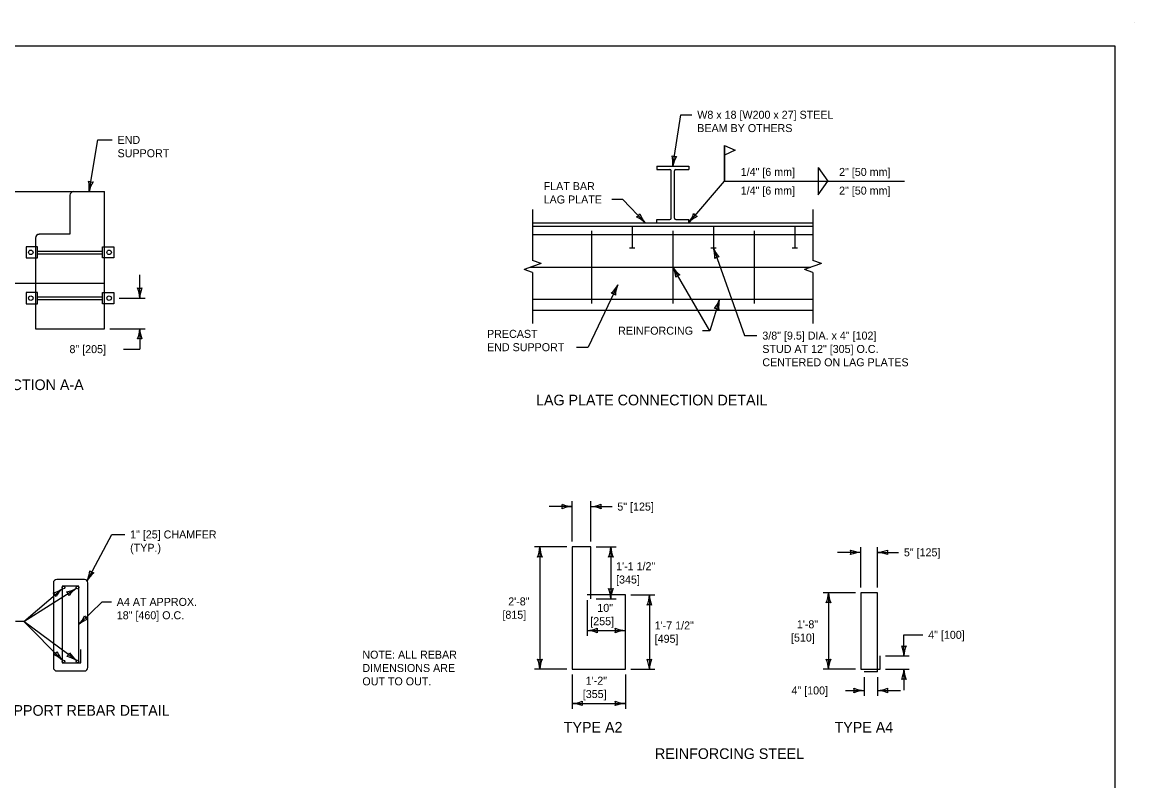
# Model space of a CAD drawing. Extents: x 49987.2 to 50044, y 49982.5 to 50011.4.
# Drawn here: x 50008.56 to 50016.9, y 49993.49 to 49999.18 of the extents above; entities that cross this region are included whole.
import ezdxf

# ---------------------------------------------------------------- set-up
doc = ezdxf.new("R2010")
doc.units = 0
for name, color, linetype in [('Level 1', 7, 'Continuous'), ('Level 2', 7, 'Continuous'), ('Level 3', 7, 'Continuous'), ('Level 4', 7, 'Continuous'), ('Level 5', 7, 'Continuous'), ('Level 6', 7, 'Continuous')]:
    doc.layers.add(name, color=color, linetype=linetype)

msp = doc.modelspace()

# ---------------------------------------------------------------- linework, layer by layer
at = {"layer": 'Level 1'}
for p, q in [((50016.9001, 49999.1756), (50016.9001, 49999.1756)), ((50013.3156, 49998.0969), (50013.5556, 49998.0969)), ((50013.3156, 49998.0969), (50013.3156, 49998.0719)), ((50013.3156, 49998.0719), (50013.4131, 49998.0719)), ((50013.4581, 49998.0719), (50013.5556, 49998.0719)), ((50013.5556, 49998.0969), (50013.5556, 49998.0719)), ((50013.4231, 49997.7069), (50013.4231, 49998.0619)), ((50013.4481, 49997.7069), (50013.4481, 49998.0619)), ((50007.5791, 49997.9057), (50009.174, 49997.9057)), ((50009.174, 49996.8763), (50009.174, 49997.9057)), ((50008.9153, 49997.8776), (50008.9153, 49997.5851)), ((50012.3846, 49997.6719), (50014.4864, 49997.6719)), ((50013.3156, 49997.6719), (50013.3156, 49997.6969)), ((50013.3156, 49997.6969), (50013.4131, 49997.6969)), ((50013.4581, 49997.6969), (50013.5556, 49997.6969)), ((50013.5556, 49997.6719), (50013.5556, 49997.6969)), ((50008.9153, 49997.5851), (50008.6847, 49997.5851)), ((50012.3846, 49997.6469), (50014.4864, 49997.6469)), ((50014.4864, 49997.5806), (50012.3846, 49997.5806)), ((50012.8256, 49997.6106), (50012.8256, 49997.0669)), ((50013.1306, 49997.6469), (50013.1306, 49997.4819)), ((50013.4356, 49997.6106), (50013.4356, 49997.0669)), ((50013.7406, 49997.6469), (50013.7406, 49997.4819)), ((50014.0456, 49997.6106), (50014.0456, 49997.0669)), ((50014.3506, 49997.6469), (50014.3506, 49997.4819)), ((50008.6565, 49997.5569), (50008.6565, 49996.8763)), ((50008.6712, 49997.46), (50009.1594, 49997.46)), ((50008.6712, 49997.44), (50009.1594, 49997.44)), ((50013.1506, 49997.4819), (50013.1106, 49997.4819)), ((50013.7606, 49997.4819), (50013.7206, 49997.4819)), ((50014.3706, 49997.4819), (50014.3306, 49997.4819)), ((50012.3692, 49997.3387), (50014.471, 49997.3387)), ((50007.5791, 49997.2194), (50008.6565, 49997.2194)), ((50008.6712, 49997.1169), (50009.1594, 49997.1169)), ((50008.6712, 49997.0969), (50009.1594, 49997.0969)), ((50014.4864, 49997.0969), (50012.3846, 49997.0969)), ((50012.3846, 49997.0169), (50014.4864, 49997.0169)), ((50008.6565, 49996.8763), (50009.174, 49996.8763)), ((50012.822, 49995.2403), (50012.6814, 49995.2403)), ((50012.6814, 49995.2403), (50012.6814, 49994.3234)), ((50012.822, 49994.8522), (50012.822, 49995.2403)), ((50009.0248, 49994.9971), (50008.816, 49994.9971)), ((50008.791, 49994.9721), (50008.791, 49994.3358)), ((50008.8574, 49994.9463), (50008.8574, 49994.3725)), ((50008.9824, 49994.9463), (50008.8574, 49994.9463)), ((50008.9824, 49994.3725), (50008.9824, 49994.9463)), ((50009.0498, 49994.3358), (50009.0498, 49994.9721)), ((50013.0807, 49994.8803), (50012.7939, 49994.8803)), ((50013.0807, 49994.3234), (50013.0807, 49994.8803)), ((50014.8457, 49994.8972), (50014.8457, 49994.3234)), ((50014.9707, 49994.8972), (50014.8457, 49994.8972)), ((50014.9707, 49994.3043), (50014.9707, 49994.8972)), ((50008.9981, 49994.3725), (50008.9981, 49994.4715)), ((50014.9898, 49994.3234), (50014.9898, 49994.4234)), ((50008.8574, 49994.3725), (50008.9981, 49994.3725)), ((50012.6814, 49994.3234), (50013.0807, 49994.3234)), ((50014.8457, 49994.3234), (50014.9898, 49994.3234)), ((50008.816, 49994.3108), (50009.0248, 49994.3108)), ((50014.9707, 49994.3043), (50014.8707, 49994.3043))]:
    msp.add_line(p, q, dxfattribs=at)
for points in [[(49999.3835, 49998.9992), (50016.7501, 49998.9992), (50016.7501, 49987.7988), (49999.3835, 49987.7988)], [(50008.5868, 49997.4079), (50008.6712, 49997.4079), (50008.6712, 49997.4922), (50008.5868, 49997.4922)], [(50009.2438, 49997.4079), (50009.1594, 49997.4079), (50009.1594, 49997.4922), (50009.2438, 49997.4922)], [(50008.5868, 49997.0647), (50008.6712, 49997.0647), (50008.6712, 49997.1491), (50008.5868, 49997.1491)], [(50009.2438, 49997.0647), (50009.1594, 49997.0647), (50009.1594, 49997.1491), (50009.2438, 49997.1491)]]:
    msp.add_lwpolyline(points, close=True, dxfattribs=at)
for centre, radius in [((50008.6216, 49997.45), 0.0169), ((50009.2089, 49997.45), 0.0169), ((50008.6216, 49997.1069), 0.0169), ((50009.2089, 49997.1069), 0.0169), ((50008.8674, 49994.9363), 0.01), ((50008.9724, 49994.9363), 0.01), ((50008.8674, 49994.3825), 0.01), ((50008.9724, 49994.3825), 0.01)]:
    msp.add_circle(centre, radius, dxfattribs=at)
for centre, radius, start, end in [((50013.4131, 49998.0619), 0.01, 360, 90), ((50013.4581, 49998.0619), 0.01, 90, 180), ((50008.9434, 49997.8776), 0.0281, 90, 180), ((50013.4131, 49997.7069), 0.01, 270, 360), ((50013.4581, 49997.7069), 0.01, 180, 270), ((50008.6847, 49997.5569), 0.0281, 90, 180), ((50008.816, 49994.9721), 0.025, 90, 180), ((50009.0248, 49994.9721), 0.025, 0, 90), ((50008.816, 49994.3358), 0.025, 180, 270), ((50009.0248, 49994.3358), 0.025, 270, 0)]:
    msp.add_arc(centre, radius, start, end, dxfattribs=at)
at = {"layer": 'Level 3'}
for p, q in [((50013.4356, 49998.0969), (50013.4951, 49998.4819)), ((50013.4951, 49998.4819), (50013.5795, 49998.4819)), ((50009.0587, 49997.9057), (50009.1254, 49998.2932)), ((50009.1254, 49998.2932), (50009.2324, 49998.2932)), ((50013.8228, 49998.2504), (50013.9026, 49998.2151)), ((50013.8228, 49998.2504), (50013.8228, 49997.983)), ((50013.8228, 49997.983), (50013.8228, 49998.2504)), ((50013.8228, 49997.983), (50013.8228, 49998.2504)), ((50013.9026, 49998.2151), (50013.8228, 49998.1799)), ((50014.5261, 49998.0856), (50014.5261, 49997.8805)), ((50014.5261, 49998.0856), (50014.5993, 49997.983)), ((50013.5556, 49997.6719), (50013.8228, 49997.983)), ((50013.8228, 49997.983), (50015.1745, 49997.983)), ((50014.5261, 49997.8805), (50014.5993, 49997.983)), ((50013.0625, 49997.8463), (50012.9791, 49997.8463)), ((50013.2293, 49997.6719), (50013.0625, 49997.8463)), ((50013.7406, 49997.4819), (50013.9739, 49996.8255)), ((50013.7146, 49996.8623), (50013.4356, 49997.3387)), ((50009.4387, 49997.1069), (50009.4387, 49997.2804)), ((50013.023, 49997.2052), (50012.8004, 49996.7387)), ((50013.7864, 49997.0969), (50013.7146, 49996.8623)), ((50009.214, 49996.8763), (50009.4787, 49996.8763)), ((50009.4387, 49996.8763), (50009.4387, 49996.724)), ((50013.7146, 49996.8623), (50013.6597, 49996.8623)), ((50013.9739, 49996.8255), (50014.0674, 49996.8255)), ((50012.7131, 49996.7387), (50012.8004, 49996.7387)), ((50009.3167, 49996.724), (50009.4387, 49996.724)), ((50012.6814, 49995.2803), (50012.6814, 49995.5833)), ((50012.822, 49995.2803), (50012.822, 49995.5833)), ((50012.6814, 49995.5433), (50012.5079, 49995.5433)), ((50012.822, 49995.5433), (50012.9801, 49995.5433)), ((50009.0446, 49994.9873), (50009.2289, 49995.3344)), ((50009.2289, 49995.3344), (50009.3265, 49995.3344)), ((50012.6414, 49995.2403), (50012.3987, 49995.2403)), ((50012.4387, 49995.2403), (50012.4387, 49994.3234)), ((50012.862, 49995.2403), (50013.0109, 49995.2403)), ((50012.9709, 49995.2403), (50012.9709, 49994.8522)), ((50014.8457, 49994.9372), (50014.8457, 49995.2402)), ((50014.9707, 49994.9372), (50014.9707, 49995.2402)), ((50014.8457, 49995.2002), (50014.6723, 49995.2002)), ((50014.9707, 49995.2002), (50015.1289, 49995.2002)), ((50008.5685, 49994.682), (50008.964, 49994.9309)), ((50008.5685, 49994.682), (50008.8598, 49994.9298)), ((50008.9824, 49994.6594), (50009.1569, 49994.8283)), ((50009.1569, 49994.8283), (50009.2265, 49994.8283)), ((50012.7939, 49994.8403), (50012.7939, 49994.5737)), ((50012.862, 49994.8522), (50013.0109, 49994.8522)), ((50013.1207, 49994.8803), (50013.3002, 49994.8803)), ((50013.2602, 49994.8803), (50013.2602, 49994.3234)), ((50014.8057, 49994.8972), (50014.5631, 49994.8972)), ((50014.6031, 49994.8972), (50014.6031, 49994.3234)), ((50008.5685, 49994.682), (50008.5063, 49994.682)), ((50008.8603, 49994.3896), (50008.5685, 49994.682)), ((50008.9644, 49994.3884), (50008.5685, 49994.682)), ((50012.7939, 49994.6137), (50013.0807, 49994.6137)), ((50015.1693, 49994.4234), (50015.1693, 49994.5815)), ((50015.1693, 49994.5815), (50015.3112, 49994.5815)), ((50015.0298, 49994.4234), (50015.2093, 49994.4234)), ((50012.6414, 49994.3234), (50012.3987, 49994.3234)), ((50013.1207, 49994.3234), (50013.3002, 49994.3234)), ((50014.8057, 49994.3234), (50014.5631, 49994.3234)), ((50015.0298, 49994.3234), (50015.2093, 49994.3234)), ((50015.1693, 49994.3234), (50015.1693, 49994.1653)), ((50012.6814, 49994.2834), (50012.6814, 49994.0275)), ((50013.0807, 49994.2834), (50013.0807, 49994.0275)), ((50014.8707, 49994.2643), (50014.8707, 49994.1244)), ((50014.9707, 49994.2643), (50014.9707, 49994.1244)), ((50014.7308, 49994.1644), (50014.8707, 49994.1644)), ((50014.9707, 49994.1644), (50015.1442, 49994.1644)), ((50012.6814, 49994.0675), (50013.0807, 49994.0675))]:
    msp.add_line(p, q, dxfattribs=at)
for centre, radius, start, end in [((50013.4552, 49998.2236), 0.0548, 243.35801, 279.08037), ((50013.2039, 49998.121), 0.233, 354.0465, 13.29635), ((50013.6538, 49998.0539), 0.2223, 148.6752, 168.85871), ((50009.0805, 49998.032), 0.0548, 242.37449, 278.09685), ((50008.8274, 49997.9338), 0.233, 353.06298, 12.31283), ((50009.2761, 49997.859), 0.2223, 147.69168, 167.87519), ((50013.1407, 49997.7645), 0.0548, 295.87027, 331.59263), ((50013.3962, 49997.8188), 0.2223, 201.18746, 221.37097), ((50013.3716, 49997.8147), 0.233, 322.18114, 341.43099), ((50013.6391, 49997.7692), 0.0548, 211.49264, 247.21501), ((50013.0691, 49997.5027), 0.233, 46.55876, 65.80861), ((50013.7182, 49997.5202), 0.2223, 116.80984, 136.99334), ((50013.5282, 49997.4161), 0.2223, 357.02426, 17.20777), ((50013.956, 49997.5706), 0.233, 202.39556, 221.64541), ((50013.7836, 49997.3611), 0.0548, 91.70707, 127.42943), ((50013.2393, 49997.2344), 0.2223, 7.80724, 27.99075), ((50013.6306, 49997.4662), 0.233, 213.17854, 232.42839), ((50013.5004, 49997.2281), 0.0548, 102.49005, 138.21241), ((50009.2165, 49997.0978), 0.2223, 2.36048, 22.54399), ((50009.4387, 49997.2351), 0.0548, 252.13882, 287.86118), ((50009.6714, 49997.0954), 0.233, 157.92284, 177.17269), ((50012.8264, 49997.3091), 0.2223, 311.94577, 332.12928), ((50013.2379, 49997.1153), 0.233, 157.31707, 176.56692), ((50012.9678, 49997.0895), 0.0548, 46.62858, 82.35094), ((50013.5766, 49997.1706), 0.2223, 320.44787, 340.63138), ((50014.0123, 49997.0398), 0.233, 165.81917, 185.06902), ((50013.7489, 49996.9743), 0.0548, 55.13068, 90.85304), ((50009.2165, 49996.8854), 0.2223, 337.45601, 357.63952), ((50009.6714, 49996.8878), 0.233, 182.82731, 202.07716), ((50009.4387, 49996.7481), 0.0548, 72.13882, 107.86118), ((50012.5531, 49995.5433), 0.0548, 342.13882, 17.86118), ((50012.6929, 49995.7761), 0.233, 247.92284, 267.17269), ((50012.6905, 49995.3212), 0.2223, 92.36048, 112.54399), ((50012.8105, 49995.7761), 0.233, 272.82731, 292.07716), ((50012.8128, 49995.3212), 0.2223, 67.45601, 87.63952), ((50012.9502, 49995.5433), 0.0548, 162.13882, 197.86118), ((50012.2166, 49995.2495), 0.2223, 337.45601, 357.63952), ((50012.6714, 49995.2518), 0.233, 182.82731, 202.07716), ((50012.7487, 49995.2495), 0.2223, 337.45601, 357.63952), ((50013.2036, 49995.2518), 0.233, 182.82731, 202.07716), ((50012.4387, 49995.1121), 0.0548, 72.13882, 107.86118), ((50012.9709, 49995.1121), 0.0548, 72.13882, 107.86118), ((50014.7175, 49995.2002), 0.0548, 342.13882, 17.86118), ((50014.8572, 49995.4329), 0.233, 247.92284, 267.17269), ((50014.8549, 49994.9781), 0.2223, 92.36048, 112.54399), ((50014.9592, 49995.4329), 0.233, 272.82731, 292.07716), ((50014.9616, 49994.9781), 0.2223, 67.45601, 87.63952), ((50015.099, 49995.2002), 0.0548, 162.13882, 197.86118), ((50008.8337, 49995.0863), 0.233, 334.85483, 354.10468), ((50009.2365, 49994.875), 0.2223, 129.48353, 149.66704), ((50009.1047, 49995.1005), 0.0548, 224.16634, 259.8887), ((50008.7263, 49995.1076), 0.2223, 286.71601, 306.89951), ((50009.016, 49994.7569), 0.233, 132.08731, 151.33716), ((50008.8543, 49995.1243), 0.2223, 279.37653, 299.56004), ((50008.8551, 49994.8631), 0.0548, 14.05934, 49.7817), ((50009.0968, 49994.7395), 0.233, 124.74783, 143.99768), ((50012.9709, 49994.9804), 0.0548, 252.13882, 287.86118), ((50012.7382, 49994.8407), 0.233, 2.82731, 22.07716), ((50013.193, 49994.843), 0.2223, 157.45601, 177.63952), ((50008.7605, 49994.8486), 0.0548, 21.39881, 57.12118), ((50013.0381, 49994.8895), 0.2223, 337.45601, 357.63952), ((50013.4929, 49994.8918), 0.233, 182.82731, 202.07716), ((50014.3809, 49994.9063), 0.2223, 337.45601, 357.63952), ((50014.6031, 49994.769), 0.0548, 72.13882, 107.86118), ((50014.8358, 49994.9087), 0.233, 182.82731, 202.07716), ((50013.2602, 49994.7521), 0.0548, 72.13882, 107.86118), ((50008.8123, 49994.8186), 0.233, 316.90474, 336.15459), ((50009.1304, 49994.4934), 0.2223, 111.53344, 131.71694), ((50009.0745, 49994.7486), 0.0548, 206.21624, 241.93861), ((50012.7824, 49994.8464), 0.233, 272.82731, 292.07716), ((50012.7847, 49994.3916), 0.2223, 67.45601, 87.63952), ((50012.9221, 49994.6137), 0.0548, 162.13882, 197.86118), ((50013.0899, 49994.8358), 0.2223, 247.45601, 267.63952), ((50012.9525, 49994.6137), 0.0548, 342.13882, 17.86118), ((50013.0922, 49994.381), 0.233, 92.82731, 112.07716), ((50015.1693, 49994.5516), 0.0548, 252.13882, 287.86118), ((50014.9366, 49994.4119), 0.233, 2.82731, 22.07716), ((50015.3915, 49994.4143), 0.2223, 157.45601, 177.63952), ((50008.7698, 49994.4803), 0.0548, 297.07584, 332.7982), ((50008.7037, 49994.2171), 0.233, 47.76433, 67.01418), ((50009.024, 49994.54), 0.2223, 202.39303, 222.57654), ((50008.8612, 49994.4645), 0.0548, 305.75084, 341.4732), ((50008.8356, 49994.1943), 0.233, 56.43933, 75.68918), ((50009.1036, 49994.5618), 0.2223, 211.06803, 231.25154), ((50012.4387, 49994.4516), 0.0548, 252.13882, 287.86118), ((50012.206, 49994.3119), 0.233, 2.82731, 22.07716), ((50012.6608, 49994.3143), 0.2223, 157.45601, 177.63952), ((50013.2602, 49994.4516), 0.0548, 252.13882, 287.86118), ((50013.0275, 49994.3119), 0.233, 2.82731, 22.07716), ((50013.4824, 49994.3143), 0.2223, 157.45601, 177.63952), ((50014.6031, 49994.4516), 0.0548, 252.13882, 287.86118), ((50014.3703, 49994.3119), 0.233, 2.82731, 22.07716), ((50014.8252, 49994.3143), 0.2223, 157.45601, 177.63952), ((50014.9366, 49994.3349), 0.233, 337.92284, 357.17269), ((50015.3915, 49994.3326), 0.2223, 182.36048, 202.54399), ((50015.1693, 49994.1952), 0.0548, 72.13882, 107.86118), ((50014.8799, 49994.3865), 0.2223, 247.45601, 267.63952), ((50014.7425, 49994.1644), 0.0548, 342.13882, 17.86118), ((50014.8822, 49993.9317), 0.233, 92.82731, 112.07716), ((50014.9592, 49994.3971), 0.233, 272.82731, 292.07716), ((50014.9616, 49993.9423), 0.2223, 67.45601, 87.63952), ((50015.099, 49994.1644), 0.0548, 162.13882, 197.86118), ((50012.6699, 49994.3002), 0.233, 272.82731, 292.07716), ((50012.6722, 49993.8454), 0.2223, 67.45601, 87.63952), ((50012.8096, 49994.0675), 0.0548, 162.13882, 197.86118), ((50013.0899, 49994.2896), 0.2223, 247.45601, 267.63952), ((50012.9525, 49994.0675), 0.0548, 342.13882, 17.86118), ((50013.0922, 49993.8348), 0.233, 92.82731, 112.07716)]:
    msp.add_arc(centre, radius, start, end, dxfattribs=at)
at = {"layer": 'Level 4'}
msp.add_line((50008.6565, 49997.2194), (50009.174, 49997.2194), dxfattribs=at)
at = {"layer": 'Level 5'}
msp.add_line((50009.2838, 49997.1069), (50009.4787, 49997.1069), dxfattribs=at)
at = {"layer": 'Level 6'}
for p, q in [((50012.3846, 49997.7719), (50012.3846, 49997.3896)), ((50014.4864, 49997.7719), (50014.4864, 49997.3896)), ((50012.3846, 49997.3442), (50012.3206, 49997.3215)), ((50012.3846, 49997.2988), (50012.3206, 49997.3215)), ((50012.4486, 49997.3669), (50012.3846, 49997.3896)), ((50012.4486, 49997.3669), (50012.3846, 49997.3442)), ((50014.4864, 49997.3442), (50014.4224, 49997.3215)), ((50014.4864, 49997.2988), (50014.4224, 49997.3215)), ((50014.5504, 49997.3669), (50014.4864, 49997.3896)), ((50014.5504, 49997.3669), (50014.4864, 49997.3442)), ((50012.3846, 49997.2988), (50012.3846, 49996.9169)), ((50014.4864, 49997.2988), (50014.4864, 49996.9169))]:
    msp.add_line(p, q, dxfattribs=at)

# ---------------------------------------------------------------- texts
at = {"layer": 'Level 2'}
for s, height, p in [('W8 x 18 [W200 x 27] STEEL', 0.06, (50013.6195, 49998.4519)), ('BEAM BY OTHERS', 0.06, (50013.6195, 49998.3519)), ('END', 0.06, (50009.2724, 49998.2632)), ('SUPPORT', 0.06, (50009.2724, 49998.1632)), ('1/4" [6 mm]', 0.06, (50013.9451, 49998.023)), ('2" [50 mm]', 0.06, (50014.6831, 49998.023)), ('FLAT BAR', 0.06, (50012.4676, 49997.9163)), ('1/4" [6 mm]', 0.06, (50013.9451, 49997.883)), ('2" [50 mm]', 0.06, (50014.6831, 49997.883)), ('LAG PLATE', 0.06, (50012.4676, 49997.8163)), ('PRECAST', 0.06, (50012.0431, 49996.8087)), ('REINFORCING', 0.06, (50013.0259, 49996.8323)), ('3/8" [9.5] DIA. x 4" [102]', 0.06, (50014.1074, 49996.7955)), ('8" [205]', 0.06, (50008.9118, 49996.694)), ('END SUPPORT', 0.06, (50012.0431, 49996.7087)), ('STUD AT 12" [305] O.C.', 0.06, (50014.1074, 49996.6955)), ('CENTERED ON LAG PLATES', 0.06, (50014.1074, 49996.5955)), ('END SUPPORT SECTION A-A', 0.08, (50007.5325, 49996.4168)), ('LAG PLATE CONNECTION DETAIL', 0.08, (50012.4104, 49996.3023)), ('5" [125]', 0.06, (50013.0201, 49995.5133)), ('1" [25] CHAMFER', 0.06, (50009.3665, 49995.3044)), ('(TYP.)', 0.06, (50009.3665, 49995.2044)), ('5" [125]', 0.06, (50015.1689, 49995.1702)), ('1\'-1 1/2"', 0.06, (50013.0109, 49995.0662)), ('[345]', 0.06, (50013.0109, 49994.9662)), ('A4 AT APPROX.', 0.06, (50009.2665, 49994.7983)), ('2\'-8"', 0.06, (50012.2018, 49994.8021)), ('18" [460] O.C.', 0.06, (50009.2665, 49994.6983)), ('[815]', 0.06, (50012.1583, 49994.7021)), ('10"', 0.06, (50012.87, 49994.7537)), ('[255]', 0.06, (50012.8171, 49994.6537)), ('1\'-7 1/2"', 0.06, (50013.3002, 49994.6219)), ('1\'-8"', 0.06, (50014.3661, 49994.6307)), ('[495]', 0.06, (50013.3002, 49994.5219)), ('[510]', 0.06, (50014.3226, 49994.5307)), ('4" [100]', 0.06, (50015.3512, 49994.5515)), ('NOTE: ALL REBAR', 0.06, (50011.1081, 49994.4028)), ('DIMENSIONS ARE', 0.06, (50011.1081, 49994.3028)), ('OUT TO OUT.', 0.06, (50011.1081, 49994.2028)), ('1\'-2"', 0.06, (50012.7829, 49994.2075)), ('[355]', 0.06, (50012.7612, 49994.1075)), ('4" [100]', 0.06, (50014.3259, 49994.1344)), ('LATERAL SUPPORT REBAR DETAIL', 0.08, (50007.8378, 49993.9747)), ('TYPE A2', 0.08, (50012.6186, 49993.848)), ('TYPE A4', 0.08, (50014.6488, 49993.848)), ('REINFORCING STEEL', 0.08, (50013.3025, 49993.6504))]:
    msp.add_text(s, height=height, dxfattribs=at).set_placement(p)

doc.saveas('drawing.dxf')
